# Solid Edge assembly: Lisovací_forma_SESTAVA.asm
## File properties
Author: jachy
Template: ISO Metric Assembly.asm
Last saved by: jachy
Revision: 19
Application: Solid Edge
Username: jachy
Typ obsahu dokumentu: 1
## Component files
Tvarnik.stp
E_1200_10x20.stp
E_1200_10x55.stp
Tvarnice.stp
E_1300_16x32.stp
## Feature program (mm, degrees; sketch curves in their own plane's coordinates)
body "unnamed Body 1"
body "unnamed Body 2"
body "unnamed Body 3"
body "unnamed Body 4"
body "unnamed Body 5"
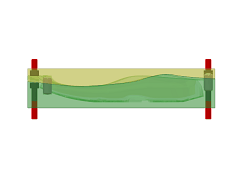
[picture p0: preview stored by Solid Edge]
